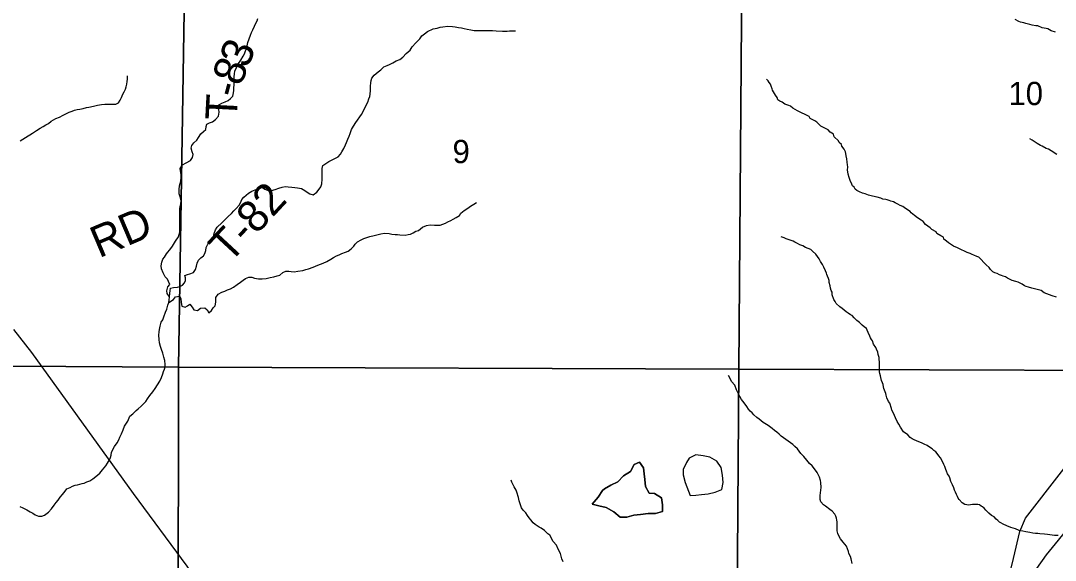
# Model space of a CAD drawing. Extents: x 0 to 34, y 0 to 22.
# Drawn here: x 3.881 to 5.747, y 18.793 to 19.765 of the extents above; entities that cross this region are included whole.
import ezdxf

# ---------------------------------------------------------------- set-up
doc = ezdxf.new("R2010")
doc.units = 0
for name, color, linetype in [('GM_X_Corporation', 7, 'Continuous'), ('GM_X_County_Road', 7, 'Continuous'), ('GM_X_Minor_Lake', 7, 'Continuous'), ('GM_X_Minor_River', 7, 'Continuous'), ('GM_X_Rail_Line', 7, 'Continuous'), ('GM_X_Section_Text', 7, 'Continuous'), ('GM_X_Township_Road_Text', 7, 'Continuous')]:
    doc.layers.add(name, color=color, linetype=linetype)

msp = doc.modelspace()

# ---------------------------------------------------------------- linework, layer by layer
at = {"layer": 'GM_X_Corporation'}
for points in [[(3.1676, 20.1592), (4.1816, 20.1598), (4.1654, 19.1412), (3.1497, 19.1471)], [(5.1838, 20.1584), (5.1759, 19.1377), (4.1654, 19.1412), (4.1816, 20.1598)], [(5.1838, 20.1584), (6.2147, 20.1499), (6.2057, 19.1338), (5.1759, 19.1377)], [(4.1654, 19.1412), (4.1647, 18.1352), (3.1398, 18.1413), (3.1497, 19.1471)], [(4.1654, 19.1412), (5.1759, 19.1377), (5.169, 18.1258), (4.1647, 18.1352)]]:
    msp.add_lwpolyline(points, close=True, dxfattribs=at)
msp.add_lwpolyline([(5.169, 18.1258), (5.1759, 19.1377), (6.2057, 19.1338)], dxfattribs=at)
at = {"layer": 'GM_X_County_Road'}
for points in [[(4.3449, 18.425), (4.3444, 18.4716), (4.3475, 18.5521), (4.3483, 18.5869), (4.346, 18.602), (4.3336, 18.6179), (4.2747, 18.6589), (4.2565, 18.674), (4.2414, 18.6953), (4.1814, 18.7824), (4.0847, 18.9132), (3.901, 19.1674), (3.8689, 19.2091)], [(5.3963, 17.9993), (5.3968, 18.009), (5.4016, 18.0479), (5.3978, 18.0781), (5.3954, 18.0954), (5.393, 18.1234), (5.3902, 18.143), (5.3894, 18.1664), (5.3935, 18.193), (5.4031, 18.2195), (5.443, 18.3074), (5.454, 18.3285), (5.5159, 18.433), (5.543, 18.4977), (5.5848, 18.5904), (5.6376, 18.6867), (5.649, 18.7101), (5.6532, 18.7217), (5.6584, 18.7421), (5.6712, 18.7963), (5.6827, 18.8452), (5.6928, 18.8692), (5.8878, 19.1197)]]:
    msp.add_lwpolyline(points, dxfattribs=at)
at = {"layer": 'GM_X_Minor_Lake'}
for points in [[(5.0864, 18.9771), (5.0817, 18.9692), (5.0758, 18.9564), (5.0759, 18.9469), (5.0795, 18.9335), (5.0885, 18.9097)], [(5.0885, 18.9097), (5.0987, 18.9107), (5.1086, 18.9116), (5.1208, 18.9129), (5.1333, 18.9157), (5.1456, 18.9208), (5.1477, 18.9333), (5.1465, 18.9466), (5.1441, 18.96), (5.1364, 18.9719), (5.124, 18.979), (5.1119, 18.9811), (5.0983, 18.9829), (5.0864, 18.9771)], [(4.9301, 18.9189), (4.9227, 18.9069), (4.9118, 18.8942), (4.9239, 18.8909), (4.9371, 18.888), (4.9506, 18.8801), (4.9621, 18.8708), (4.9743, 18.8709), (4.9865, 18.8741), (4.999, 18.8758), (5.0127, 18.8774), (5.0256, 18.8771), (5.0382, 18.8811), (5.0384, 18.8932), (5.0364, 18.9058), (5.0241, 18.9137), (5.0146, 18.9142), (5.008, 18.9262), (5.0064, 18.9384), (5.0051, 18.949), (5.0041, 18.9597), (4.9971, 18.9697)], [(4.9876, 18.9657), (4.9805, 18.9533), (4.9682, 18.9452), (4.9577, 18.9344), (4.9455, 18.9285), (4.934, 18.9219), (4.9301, 18.9189)], [(4.9971, 18.9697), (4.9876, 18.9657)]]:
    msp.add_lwpolyline(points, dxfattribs=at)
at = {"layer": 'GM_X_Minor_River'}
for points in [[(4.1495, 19.2677), (4.1454, 19.2738), (4.1447, 19.2784), (4.1466, 19.2856), (4.1501, 19.2901), (4.1479, 19.2954), (4.1456, 19.2996), (4.1415, 19.3039), (4.1378, 19.3111), (4.1352, 19.3183), (4.1341, 19.3236), (4.1353, 19.3305), (4.1376, 19.3354), (4.1406, 19.3395), (4.1441, 19.3452), (4.1517, 19.3546), (4.1547, 19.3591), (4.1605, 19.3678), (4.1655, 19.3761), (4.167, 19.3802), (4.1682, 19.3844), (4.1683, 19.4011), (4.168, 19.4083), (4.1681, 19.4261), (4.1689, 19.4307), (4.17, 19.4356), (4.1705, 19.4409), (4.169, 19.4459), (4.1668, 19.4535), (4.1668, 19.4611), (4.1676, 19.4675), (4.1688, 19.472), (4.1696, 19.4762), (4.1704, 19.483), (4.1704, 19.4876), (4.1686, 19.499), (4.1728, 19.5054), (4.1797, 19.5091), (4.1873, 19.5132), (4.1907, 19.5189), (4.1919, 19.5242), (4.19, 19.5288), (4.1882, 19.5356), (4.1897, 19.5405), (4.1932, 19.545), (4.1989, 19.5503), (4.2016, 19.5548), (4.2058, 19.5612), (4.2107, 19.5654), (4.2149, 19.5695), (4.2157, 19.5748), (4.2165, 19.579), (4.2218, 19.5812), (4.2271, 19.583), (4.2324, 19.5872), (4.2378, 19.5936), (4.2389, 19.6004), (4.2382, 19.6053), (4.236, 19.6095), (4.2394, 19.6144), (4.2436, 19.617), (4.2497, 19.6193), (4.255, 19.6215), (4.2592, 19.6252), (4.2637, 19.6294), (4.2649, 19.6354), (4.2653, 19.6396), (4.2654, 19.6442), (4.2658, 19.6495), (4.2662, 19.6552), (4.2662, 19.6593), (4.2663, 19.6643), (4.2667, 19.6696), (4.2675, 19.6745), (4.2702, 19.6809), (4.2728, 19.6862), (4.2778, 19.6945), (4.2824, 19.7013), (4.2847, 19.7058), (4.2866, 19.7111), (4.2886, 19.7157), (4.2897, 19.7198), (4.2909, 19.7259), (4.2955, 19.7395), (4.2975, 19.744), (4.2994, 19.7489), (4.3025, 19.7554), (4.3052, 19.761), (4.3075, 19.7652), (4.309, 19.7693)], [(5.7474, 19.7445), (5.7395, 19.7473), (5.733, 19.7504), (5.73, 19.7515), (5.7232, 19.7527), (5.7153, 19.7558), (5.7115, 19.7563), (5.7051, 19.7575), (5.701, 19.7586), (5.6934, 19.7602), (5.69, 19.7614), (5.684, 19.7626), (5.681, 19.7641), (5.6746, 19.7672)], [(4.5303, 19.6766), (4.536, 19.6823), (4.5421, 19.6845), (4.5463, 19.6867), (4.5523, 19.6897), (4.5584, 19.693), (4.5649, 19.6956), (4.5702, 19.6998), (4.5763, 19.7062), (4.5835, 19.7122), (4.5873, 19.7182), (4.5934, 19.7254), (4.6007, 19.7329), (4.6045, 19.7378), (4.6091, 19.7419), (4.6148, 19.7456), (4.6246, 19.7505), (4.6322, 19.7519), (4.6375, 19.7538), (4.6424, 19.7545), (4.6515, 19.7552), (4.6595, 19.7551), (4.6644, 19.7543), (4.6704, 19.7531), (4.6757, 19.7523), (4.6806, 19.7511), (4.6863, 19.7499), (4.6931, 19.7487), (4.6987, 19.7479), (4.7044, 19.7475), (4.7161, 19.7474), (4.721, 19.7477), (4.7263, 19.7476), (4.7316, 19.7476), (4.7384, 19.7471), (4.7498, 19.7467), (4.7581, 19.7466), (4.7623, 19.7469), (4.7691, 19.7469), (4.7736, 19.7472)], [(3.8801, 19.5491), (3.885, 19.552), (3.8899, 19.5547), (3.9025, 19.5629), (3.9097, 19.5674), (3.9162, 19.5715), (3.9215, 19.5745), (3.9264, 19.5775), (3.931, 19.5801), (3.9363, 19.5842), (3.9446, 19.5894), (3.9511, 19.5917), (3.9579, 19.5954), (3.9686, 19.6006), (3.9739, 19.6024), (3.978, 19.6039), (3.983, 19.6054), (3.9879, 19.6061), (3.9936, 19.6072), (3.9996, 19.609), (4.0042, 19.6098), (4.0121, 19.6116), (4.0193, 19.613), (4.0265, 19.6141), (4.0329, 19.6148), (4.0371, 19.6151), (4.0416, 19.6151), (4.0481, 19.6147), (4.0526, 19.615), (4.0572, 19.6176), (4.0606, 19.6221), (4.0629, 19.6267), (4.0652, 19.6327), (4.0675, 19.6369), (4.0698, 19.6418), (4.071, 19.6459), (4.0722, 19.6512), (4.073, 19.6558), (4.0734, 19.66), (4.0738, 19.6657)], [(4.1495, 19.2677), (4.1503, 19.2742), (4.1504, 19.2787), (4.1512, 19.2833), (4.1568, 19.2844), (4.164, 19.2851), (4.1682, 19.2862), (4.1731, 19.2888), (4.1766, 19.2929), (4.1781, 19.2974), (4.1782, 19.302), (4.177, 19.3062), (4.1816, 19.308), (4.1858, 19.3091), (4.1926, 19.3117), (4.1964, 19.317), (4.1983, 19.3231), (4.1995, 19.3287), (4.2018, 19.3336), (4.206, 19.3378), (4.211, 19.3419), (4.2133, 19.3461), (4.2148, 19.3514), (4.2156, 19.3567), (4.2183, 19.3627), (4.2221, 19.3672), (4.2263, 19.371), (4.2286, 19.3755), (4.2302, 19.3819), (4.2321, 19.3888), (4.2355, 19.3933), (4.2435, 19.4012), (4.25, 19.4072), (4.2553, 19.4124), (4.2611, 19.4181), (4.2653, 19.4226), (4.2698, 19.4271), (4.2752, 19.4331), (4.2775, 19.4373), (4.2798, 19.4429), (4.2832, 19.4475), (4.2874, 19.4512), (4.2916, 19.4546), (4.2977, 19.458), (4.3071, 19.4617), (4.3121, 19.4639), (4.317, 19.4646), (4.3211, 19.4619), (4.3275, 19.4596), (4.3332, 19.4595), (4.34, 19.461), (4.3465, 19.4636), (4.3525, 19.4654), (4.3578, 19.4665), (4.3635, 19.4661), (4.3699, 19.4653), (4.3756, 19.4648), (4.3805, 19.464), (4.3873, 19.4628), (4.3933, 19.4593), (4.3979, 19.4566), (4.4024, 19.4536), (4.4084, 19.4516), (4.4149, 19.4565), (4.4191, 19.4618), (4.4225, 19.4659), (4.4241, 19.4716), (4.4249, 19.4795), (4.425, 19.4898), (4.4246, 19.494), (4.4246, 19.4989), (4.4262, 19.5046), (4.4368, 19.5117), (4.444, 19.5154), (4.4535, 19.5202), (4.4577, 19.5251), (4.4604, 19.5293), (4.4639, 19.5353), (4.4669, 19.5414), (4.4685, 19.5459), (4.4712, 19.5516), (4.4735, 19.5572), (4.4754, 19.5618), (4.4777, 19.5693), (4.4812, 19.575), (4.4854, 19.5818), (4.4957, 19.5965), (4.5026, 19.6101), (4.5049, 19.6142), (4.5068, 19.6188), (4.5091, 19.6244), (4.5107, 19.6286), (4.5111, 19.6332), (4.5119, 19.6396), (4.5119, 19.6476), (4.5124, 19.6533), (4.5128, 19.6574), (4.5143, 19.6616), (4.5185, 19.6669), (4.5254, 19.6729), (4.5303, 19.6766)], [(5.317, 19.5824), (5.3132, 19.5847), (5.3049, 19.5889), (5.3027, 19.5928), (5.297, 19.5958), (5.2876, 19.5997), (5.2816, 19.6028), (5.2737, 19.6078), (5.2695, 19.6113), (5.2661, 19.6128), (5.259, 19.6152), (5.2541, 19.6183), (5.2499, 19.6206), (5.2462, 19.6229), (5.2454, 19.6271), (5.2421, 19.6309), (5.2402, 19.6339), (5.2383, 19.6374), (5.2365, 19.64), (5.2361, 19.6427), (5.2343, 19.6473), (5.2331, 19.6511), (5.2309, 19.6538), (5.229, 19.6572), (5.226, 19.6599)], [(5.7488, 19.2673), (5.7413, 19.2696), (5.7269, 19.275), (5.7213, 19.2789), (5.7164, 19.2805), (5.7047, 19.2836), (5.6983, 19.2852), (5.6945, 19.2864), (5.6915, 19.2875), (5.687, 19.2906), (5.6798, 19.2941), (5.6757, 19.2953), (5.6692, 19.2972), (5.6606, 19.3015), (5.6568, 19.3038), (5.6527, 19.305), (5.6496, 19.3061), (5.6462, 19.3073), (5.6421, 19.3096), (5.6376, 19.3108), (5.6342, 19.3131), (5.6297, 19.3173), (5.6274, 19.3204), (5.6222, 19.3253), (5.6087, 19.3391), (5.6053, 19.3407), (5.6, 19.3426), (5.5966, 19.3442), (5.5932, 19.3457), (5.5879, 19.3477), (5.583, 19.35), (5.5774, 19.3523), (5.5706, 19.3562), (5.5631, 19.3593), (5.554, 19.3651), (5.5503, 19.3681), (5.5457, 19.3716), (5.545, 19.375), (5.5405, 19.3777), (5.5333, 19.3819), (5.5319, 19.385), (5.5239, 19.3892), (5.5213, 19.3923), (5.5127, 19.3984), (5.5082, 19.4034), (5.5048, 19.4061), (5.4984, 19.41), (5.4931, 19.4142), (5.4871, 19.4192), (5.4852, 19.4218), (5.4769, 19.4269), (5.4717, 19.4303), (5.4672, 19.4326), (5.463, 19.4346), (5.4604, 19.4361), (5.4577, 19.4373), (5.4547, 19.4388), (5.4502, 19.4404), (5.4472, 19.4415), (5.4438, 19.4423), (5.4411, 19.4431), (5.4355, 19.4439), (5.4321, 19.4455), (5.4253, 19.4474), (5.417, 19.4494), (5.4098, 19.451), (5.4038, 19.4533), (5.3989, 19.4545), (5.3936, 19.4568), (5.3891, 19.4595), (5.3861, 19.4618), (5.3838, 19.4653), (5.3812, 19.468), (5.3797, 19.471), (5.3767, 19.4775), (5.3752, 19.4828), (5.373, 19.4889), (5.3727, 19.4931), (5.3723, 19.4961), (5.3724, 19.5018), (5.372, 19.5056), (5.3717, 19.5102), (5.371, 19.5162), (5.3699, 19.5219), (5.3691, 19.5261), (5.3684, 19.5288), (5.3658, 19.5341), (5.362, 19.5391), (5.3613, 19.5421), (5.3568, 19.5456), (5.3557, 19.5486), (5.3478, 19.5559), (5.3467, 19.5609), (5.341, 19.5643), (5.3369, 19.5685), (5.3241, 19.5755), (5.317, 19.5824)], [(5.7496, 19.5241), (5.739, 19.5306), (5.7345, 19.5337), (5.73, 19.5353), (5.7228, 19.5391), (5.7202, 19.5407), (5.7138, 19.5441), (5.7051, 19.5499), (5.701, 19.5522)], [(4.148, 19.2575), (4.1567, 19.2631), (4.1605, 19.2676), (4.1673, 19.2691), (4.1699, 19.2645), (4.1703, 19.2573), (4.1714, 19.2508), (4.1778, 19.2489), (4.1819, 19.2515), (4.1861, 19.2545), (4.1902, 19.2492), (4.1932, 19.2442), (4.1997, 19.2434), (4.2054, 19.2475), (4.2129, 19.2482), (4.2174, 19.2444), (4.2204, 19.239), (4.225, 19.2431), (4.2281, 19.2477), (4.2315, 19.2518), (4.233, 19.2582), (4.2327, 19.2624), (4.2327, 19.2666), (4.2373, 19.2726), (4.2438, 19.2764), (4.2491, 19.2782), (4.254, 19.2801), (4.2597, 19.2823), (4.265, 19.2853), (4.2715, 19.2898), (4.2772, 19.2943), (4.2821, 19.298), (4.2867, 19.301), (4.2927, 19.3032), (4.298, 19.3032), (4.3026, 19.3016), (4.3097, 19.3), (4.3165, 19.3), (4.3237, 19.3007), (4.3309, 19.3025), (4.3374, 19.3039), (4.3438, 19.3058), (4.3484, 19.3069), (4.3537, 19.3118), (4.3594, 19.314), (4.3647, 19.3139), (4.3688, 19.3135), (4.3741, 19.3131), (4.3806, 19.3138), (4.39, 19.3152), (4.395, 19.3171), (4.3999, 19.3185), (4.4086, 19.3215), (4.4169, 19.3248), (4.4215, 19.3267), (4.4264, 19.3285), (4.4329, 19.3315), (4.4405, 19.3356), (4.4454, 19.3386), (4.4507, 19.3416), (4.4553, 19.3434), (4.4602, 19.3457), (4.467, 19.3483), (4.4716, 19.3501), (4.4773, 19.3542), (4.4819, 19.3588), (4.4845, 19.3629), (4.4887, 19.3667), (4.4948, 19.3704), (4.4997, 19.3726), (4.5104, 19.3763), (4.5187, 19.3781), (4.5255, 19.38), (4.5308, 19.3814), (4.5369, 19.3825), (4.5456, 19.3817), (4.5501, 19.3809), (4.5561, 19.3801), (4.5603, 19.38), (4.5645, 19.3792), (4.5743, 19.3791), (4.5796, 19.3798), (4.5838, 19.3809), (4.5887, 19.3828), (4.5936, 19.3858), (4.5985, 19.3876), (4.6058, 19.3936), (4.6126, 19.3966), (4.6194, 19.3977), (4.627, 19.3972), (4.6315, 19.3968), (4.6372, 19.3971), (4.6425, 19.399), (4.647, 19.4008), (4.6512, 19.4027), (4.6565, 19.4053), (4.6611, 19.4079), (4.6664, 19.4105), (4.6725, 19.4143), (4.6748, 19.4184), (4.6805, 19.4233)], [(4.6805, 19.4233), (4.6873, 19.4274), (4.6923, 19.4312), (4.698, 19.4345), (4.7029, 19.4375)], [(5.4298, 19.1329), (5.4298, 19.1394), (5.4299, 19.1428), (5.4296, 19.1508), (5.4292, 19.1549), (5.4289, 19.1587), (5.4274, 19.1637), (5.4267, 19.1679), (5.4244, 19.1732), (5.4229, 19.1766), (5.4188, 19.1827), (5.417, 19.1884), (5.4155, 19.1911), (5.4136, 19.1938), (5.4121, 19.1968), (5.4095, 19.2033), (5.4077, 19.2079), (5.4062, 19.2105), (5.402, 19.2136), (5.3983, 19.217), (5.3938, 19.2213), (5.3889, 19.2251), (5.384, 19.2297), (5.3802, 19.2339), (5.3772, 19.2355), (5.3731, 19.2381), (5.3697, 19.2405), (5.3659, 19.2439), (5.3626, 19.247), (5.358, 19.25), (5.3517, 19.2558), (5.3498, 19.2592), (5.3476, 19.263), (5.3446, 19.2714), (5.3442, 19.276), (5.3428, 19.279), (5.3413, 19.2836), (5.3405, 19.2878), (5.3391, 19.2939), (5.3387, 19.2973), (5.338, 19.3007), (5.3361, 19.3049), (5.3346, 19.3079), (5.3339, 19.3106), (5.3324, 19.3144), (5.3294, 19.3213), (5.3272, 19.3262), (5.3235, 19.3316), (5.3212, 19.3361), (5.3182, 19.3403), (5.3149, 19.3445), (5.3092, 19.3499), (5.3059, 19.353), (5.2964, 19.3568), (5.2912, 19.3595), (5.2863, 19.3615), (5.2821, 19.3638), (5.2772, 19.3665), (5.2738, 19.3681), (5.2667, 19.3704), (5.2614, 19.3723), (5.2576, 19.3739), (5.2527, 19.3758)], [(3.8798, 18.8898), (3.8851, 18.8878), (3.8919, 18.884), (3.8979, 18.8805), (3.9028, 18.8778), (3.9073, 18.8751), (3.9133, 18.8728), (3.9194, 18.8727), (3.9243, 18.8742), (3.9315, 18.8798), (3.9365, 18.8858), (3.9415, 18.8926), (3.9449, 18.8971), (3.9487, 18.9016), (3.9525, 18.9069), (3.9563, 18.9118), (3.9613, 18.9175), (3.9644, 18.9216), (3.97, 18.9242), (3.9746, 18.9264), (3.9795, 18.9283), (3.9837, 18.929), (3.9917, 18.9312), (3.9958, 18.9323), (4.0004, 18.9342), (4.0057, 18.9364), (4.011, 18.9401), (4.0167, 18.9439), (4.0236, 18.9503), (4.0285, 18.9559), (4.0346, 18.9634), (4.0377, 18.9683), (4.0411, 18.974), (4.0431, 18.9785), (4.0442, 18.9827), (4.045, 18.9876), (4.0504, 18.9982), (4.055, 19.005), (4.058, 19.0103), (4.06, 19.0148), (4.063, 19.0208), (4.0657, 19.028), (4.0684, 19.0348), (4.0742, 19.0439), (4.078, 19.0529), (4.083, 19.0567), (4.0891, 19.0631), (4.0932, 19.0661), (4.0986, 19.0706), (4.1066, 19.0792), (4.11, 19.0837), (4.1142, 19.0898), (4.1192, 19.0966), (4.1234, 19.1026), (4.128, 19.1094), (4.1318, 19.1158), (4.1349, 19.1226), (4.1376, 19.129), (4.1387, 19.1332), (4.1403, 19.1373), (4.1414, 19.1419), (4.1415, 19.146), (4.1408, 19.1529), (4.1393, 19.159), (4.1371, 19.1662), (4.1352, 19.173), (4.133, 19.1784), (4.1315, 19.1848), (4.1308, 19.1909), (4.1301, 19.1985), (4.1305, 19.2046), (4.1313, 19.2091), (4.1325, 19.2148), (4.1345, 19.222), (4.1371, 19.2265), (4.1394, 19.2318), (4.1425, 19.2401), (4.1445, 19.2454), (4.1464, 19.2526), (4.148, 19.2575), (4.1487, 19.2617), (4.1495, 19.2677)], [(5.3532, 18.8507), (5.3533, 18.8621), (5.353, 18.8655), (5.3522, 18.8689), (5.3511, 18.8723), (5.3493, 18.8761), (5.3444, 18.8815), (5.3403, 18.8846), (5.3324, 18.8903), (5.329, 18.893), (5.3241, 18.8984), (5.3226, 18.9029), (5.3226, 18.9063), (5.323, 18.9098), (5.3235, 18.9147), (5.3242, 18.9196), (5.3243, 18.9245), (5.324, 18.9333), (5.3236, 18.9367), (5.3214, 18.9428), (5.3173, 18.9511), (5.3124, 18.958), (5.3083, 18.963), (5.3038, 18.9676), (5.2985, 18.9733), (5.2933, 18.9798), (5.288, 18.9852), (5.2847, 18.9894), (5.2817, 18.9936), (5.2768, 18.9982), (5.2734, 19.0016), (5.2693, 19.0047), (5.2648, 19.0078), (5.261, 19.0108), (5.2527, 19.017), (5.249, 19.0204), (5.2445, 19.0239), (5.2403, 19.027), (5.2362, 19.0304), (5.2287, 19.0358), (5.22, 19.0416), (5.2125, 19.0473), (5.2083, 19.0504), (5.2031, 19.055), (5.2001, 19.0588), (5.1967, 19.0615), (5.1937, 19.0653), (5.1907, 19.0703), (5.1855, 19.0768), (5.181, 19.0829), (5.178, 19.0882), (5.1754, 19.0928), (5.172, 19.1001), (5.1687, 19.1088), (5.1631, 19.1153), (5.1597, 19.1218), (5.1575, 19.126)], [(5.7517, 18.8375), (5.7453, 18.8379), (5.7408, 18.8383), (5.737, 18.8388), (5.7325, 18.8396), (5.7275, 18.84), (5.7189, 18.8408), (5.7151, 18.8412), (5.7113, 18.8413), (5.7064, 18.8421), (5.7007, 18.8429), (5.6939, 18.8441), (5.6879, 18.8453), (5.6815, 18.8469), (5.6747, 18.8496), (5.6664, 18.8523), (5.6592, 18.8554), (5.6528, 18.8581), (5.6487, 18.8604), (5.646, 18.862), (5.643, 18.8647), (5.6404, 18.8673), (5.6363, 18.8716), (5.6317, 18.8739), (5.6269, 18.8781), (5.6238, 18.8808), (5.6216, 18.8834), (5.6186, 18.8869), (5.6156, 18.8892), (5.613, 18.8907), (5.6103, 18.8927), (5.6069, 18.8934), (5.5975, 18.8935), (5.5941, 18.8932), (5.5907, 18.8925), (5.5835, 18.8933), (5.5786, 18.8967), (5.5733, 18.9025), (5.5715, 18.9052), (5.5703, 18.9078), (5.5685, 18.9116), (5.5666, 18.9158), (5.5651, 18.9196), (5.5637, 18.9238), (5.5614, 18.9288), (5.5584, 18.9349), (5.5566, 18.9417), (5.5551, 18.9448), (5.5521, 18.949), (5.5506, 18.9535), (5.5492, 18.9569), (5.5473, 18.9623), (5.5458, 18.9657), (5.5421, 18.9733), (5.5395, 18.9775), (5.5368, 18.9813), (5.5339, 18.9852), (5.5312, 18.9882), (5.5278, 18.9909), (5.5245, 18.994), (5.5199, 18.997), (5.5158, 18.9997), (5.5105, 19.0024), (5.5056, 19.0048), (5.5007, 19.0067), (5.4966, 19.0083), (5.4924, 19.0102), (5.4887, 19.0118), (5.4849, 19.0144), (5.4808, 19.019), (5.4733, 19.0248), (5.4673, 19.0332), (5.4643, 19.0385), (5.4617, 19.0431), (5.4583, 19.0496), (5.4565, 19.0542), (5.4542, 19.0595), (5.452, 19.0637), (5.4516, 19.0667), (5.4483, 19.0759), (5.446, 19.0793), (5.4427, 19.0858), (5.442, 19.0903), (5.4409, 19.0938), (5.4375, 19.1029), (5.4372, 19.1059), (5.4364, 19.1097), (5.4353, 19.1128), (5.4335, 19.1173), (5.4324, 19.1223), (5.4313, 19.1257), (5.4302, 19.1295), (5.4298, 19.1329)], [(5.0864, 18.9771), (5.0817, 18.9692), (5.0758, 18.9564), (5.0759, 18.9469), (5.0795, 18.9335), (5.0885, 18.9097)], [(5.0885, 18.9097), (5.0987, 18.9107), (5.1086, 18.9116), (5.1208, 18.9129), (5.1333, 18.9157), (5.1456, 18.9208), (5.1477, 18.9333), (5.1465, 18.9466), (5.1441, 18.96), (5.1364, 18.9719), (5.124, 18.979), (5.1119, 18.9811), (5.0983, 18.9829), (5.0864, 18.9771)], [(4.9971, 18.9697), (5.0041, 18.9597), (5.0051, 18.949), (5.0064, 18.9384), (5.008, 18.9262), (5.0146, 18.9142), (5.0241, 18.9137), (5.0364, 18.9058), (5.0384, 18.8932), (5.0382, 18.8811), (5.0256, 18.8771), (5.0127, 18.8774), (4.999, 18.8758), (4.9865, 18.8741), (4.9743, 18.8709), (4.9621, 18.8708), (4.9506, 18.8801), (4.9371, 18.888), (4.9239, 18.8909), (4.9118, 18.8942), (4.9227, 18.9069), (4.9301, 18.9189)], [(4.9301, 18.9189), (4.934, 18.9219), (4.9455, 18.9285), (4.9577, 18.9344), (4.9682, 18.9452), (4.9805, 18.9533), (4.9876, 18.9657)], [(4.9876, 18.9657), (4.9971, 18.9697)], [(4.8593, 18.7904), (4.8567, 18.7958), (4.8545, 18.8056), (4.85, 18.8133), (4.847, 18.8205), (4.8414, 18.827), (4.8354, 18.8381), (4.8317, 18.8408), (4.8257, 18.8465), (4.8196, 18.8507), (4.8163, 18.853), (4.8091, 18.8577), (4.8053, 18.8607), (4.8008, 18.8661), (4.7978, 18.8695), (4.7949, 18.8737), (4.7919, 18.8783), (4.7874, 18.8833), (4.784, 18.8878), (4.7821, 18.8928), (4.7799, 18.9004), (4.7785, 18.9061), (4.7759, 18.9156), (4.7744, 18.9194), (4.7707, 18.9255), (4.7692, 18.929), (4.7669, 18.9339), (4.7654, 18.9373)], [(5.3804, 18.7875), (5.3786, 18.7954), (5.3774, 18.7996), (5.3745, 18.8053), (5.3737, 18.8091), (5.37, 18.8183), (5.3644, 18.8255), (5.3595, 18.8317), (5.3565, 18.837), (5.3547, 18.8412), (5.3536, 18.8461), (5.3532, 18.8507)]]:
    msp.add_lwpolyline(points, dxfattribs=at)
at = {"layer": 'GM_X_Rail_Line'}
msp.add_lwpolyline([(5.6961, 18.7537), (5.7307, 18.8031), (5.7764, 18.8589)], dxfattribs=at)

# ---------------------------------------------------------------- texts
at = {"layer": 'GM_X_Section_Text'}
for s, height, p in [('10', 0.04186, (5.6623, 19.6133)), ('9', 0.0419, (4.6598, 19.5087))]:
    msp.add_text(s, height=height, rotation=0, dxfattribs=at).set_placement(p)
at = {"layer": 'GM_X_Township_Road_Text'}
for s, height, rotation, p in [('3', 0.0568, 67.6743, (4.29, 19.6777)), ('8', 0.0568, 69.207, (4.2777, 19.6454)), ('-', 0.0568, 75.0095, (4.2722, 19.6243)), ('T', 0.0568, 87.0417, (4.2705, 19.5849)), ('T-82', 0.05682, 47.1938, (4.2576, 19.3262)), ('RD', 0.05682, 23.0037, (4.0223, 19.3371))]:
    msp.add_text(s, height=height, rotation=rotation, dxfattribs=at).set_placement(p)

doc.saveas('drawing.dxf')
